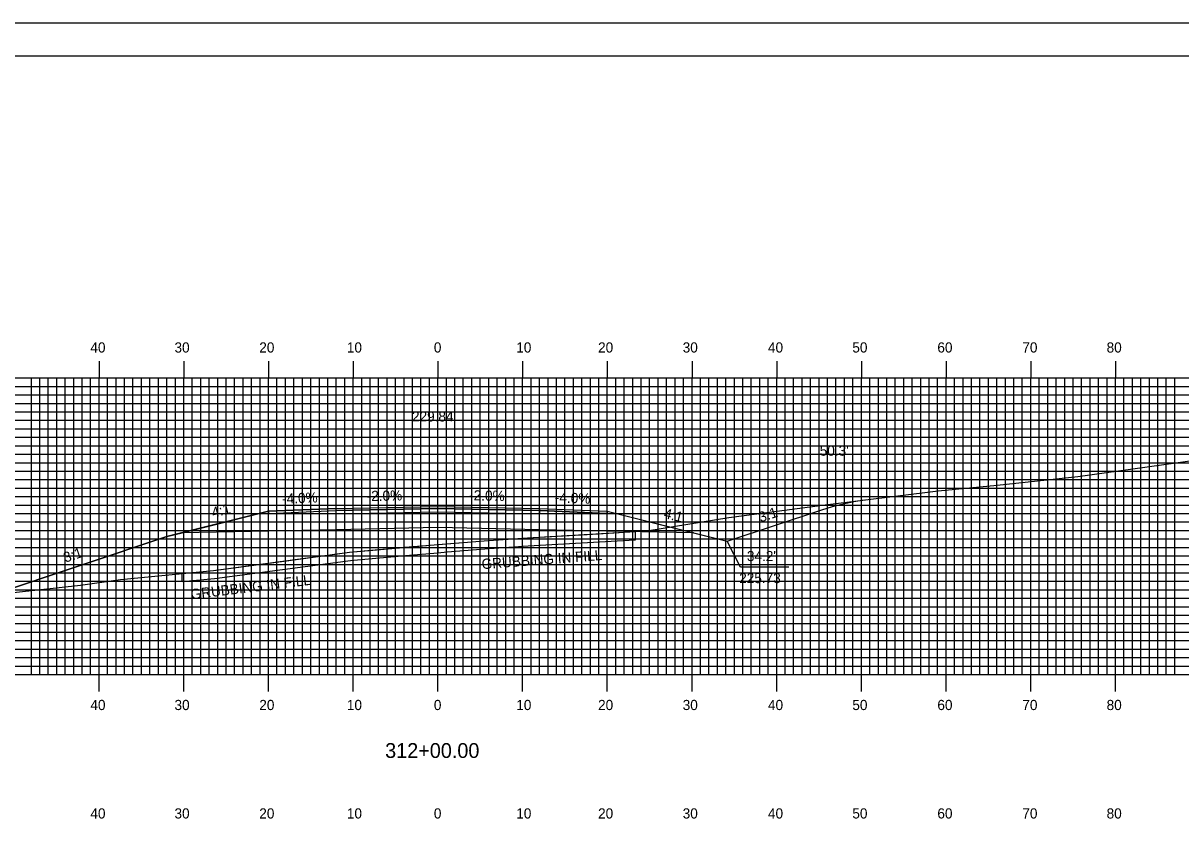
# Model space of a CAD drawing. Extents: x 1818457 to 1818800, y 442591 to 442811.
# Drawn here: x 1818573.7 to 1818710.4, y 442716.2 to 442810.5 of the extents above; entities that cross this region are included whole.
import ezdxf

# ---------------------------------------------------------------- set-up
doc = ezdxf.new("R2010")
doc.units = 0
for name, color, linetype in [('ANNOTATION', 7, 'Continuous'), ('BORDER', 7, 'Continuous'), ('D_Roadway_Centerline', 7, 'Continuous'), ('D_Roadway_Centerline_Text', 7, 'Continuous'), ('D_Roadway_Edge_Shoulder', 7, 'Continuous'), ('D_Roadway_Edge_TW', 7, 'Continuous'), ('D_Roadway_Pavement', 7, 'Continuous'), ('D_Roadway_SlopeLines', 7, 'Continuous'), ('D_Roadway_SubGrade', 7, 'Continuous'), ('D_Text_Standard', 7, 'Continuous'), ('GRUBBING IN FILL', 7, 'Continuous'), ('H_V ANNOTATION', 7, 'Continuous'), ('MAJOR', 7, 'Continuous'), ('MINOR', 7, 'Continuous'), ('PLOT BOUNDARY', 7, 'Continuous'), ('S_Roadway_Centerline', 7, 'Continuous')]:
    doc.layers.add(name, color=color, linetype=linetype)

msp = doc.modelspace()

# ---------------------------------------------------------------- linework, layer by layer
at = {"layer": 'ANNOTATION'}
msp.add_lwpolyline([(1818664.07, 442746.33), (1818658.38, 442746.33), (1818656.81, 442749.4)], dxfattribs=at)
at = {"layer": 'BORDER'}
msp.add_lwpolyline([(1818473.04, 442596.67), (1818793.04, 442596.67), (1818793.04, 442806.67), (1818473.04, 442806.67)], close=True, dxfattribs=at)
at = {"layer": 'D_Roadway_Centerline'}
msp.add_lwpolyline([(1818570, 442743.06), (1818590.64, 442749.94), (1818592.46, 442750.4), (1818602.64, 442752.94), (1818610.64, 442753.26), (1818622.64, 442753.5), (1818634.64, 442753.26), (1818642.64, 442752.94), (1818652.81, 442750.4), (1818656.81, 442749.4), (1818667.98, 442753.12), (1818669.23, 442753.51), (1818670.48, 442753.82), (1818671.73, 442754.08), (1818672.98, 442754.27)], dxfattribs=at)
at = {"layer": 'D_Roadway_Edge_Shoulder'}
for points in [[(1818610.64, 442753.26), (1818602.64, 442752.94), (1818602.64, 442752.69), (1818610.64, 442753.01)], [(1818634.64, 442753.26), (1818642.64, 442752.94), (1818642.64, 442752.69), (1818634.64, 442753.01)]]:
    msp.add_lwpolyline(points, close=True, dxfattribs=at)
at = {"layer": 'D_Roadway_Edge_TW'}
msp.add_lwpolyline([(1818610.64, 442753.01), (1818610.64, 442753.26), (1818622.64, 442753.5), (1818634.64, 442753.26), (1818634.64, 442753.01), (1818622.64, 442753.25)], close=True, dxfattribs=at)
at = {"layer": 'D_Roadway_Pavement'}
msp.add_lwpolyline([(1818610.64, 442752.59), (1818610.64, 442753.01), (1818622.64, 442753.25), (1818634.64, 442753.01), (1818634.64, 442752.59), (1818622.64, 442752.83)], close=True, dxfattribs=at)
at = {"layer": 'D_Roadway_SlopeLines'}
for points in [[(1818656.81, 442749.4), (1818667.98, 442753.12), (1818669.23, 442753.51), (1818670.48, 442753.82), (1818671.73, 442754.08), (1818672.98, 442754.27)], [(1818602.64, 442752.94), (1818590.64, 442749.94), (1818570, 442743.06)], [(1818642.64, 442752.94), (1818656.81, 442749.4)]]:
    msp.add_lwpolyline(points, dxfattribs=at)
at = {"layer": 'D_Roadway_SubGrade'}
msp.add_lwpolyline([(1818610.64, 442750.76), (1818592.46, 442750.4), (1818602.64, 442752.94), (1818602.64, 442752.69), (1818610.64, 442753.01), (1818622.64, 442753.25), (1818634.64, 442753.01), (1818642.64, 442752.69), (1818642.64, 442752.94), (1818652.81, 442750.4), (1818634.64, 442750.76), (1818622.64, 442751)], close=True, dxfattribs=at)
at = {"layer": 'GRUBBING IN FILL'}
for points in [[(1818645.92, 442750.54), (1818645.92, 442749.53), (1818639.6, 442749.18), (1818633.28, 442748.82), (1818628.71, 442748.49), (1818623.75, 442748.09), (1818622.64, 442748), (1818622.64, 442749), (1818628.62, 442749.49), (1818631.52, 442749.7), (1818633.22, 442749.81), (1818640.26, 442750.21)], [(1818645.92, 442750.54), (1818645.92, 442749.53), (1818639.6, 442749.18), (1818633.28, 442748.82), (1818628.71, 442748.49), (1818623.75, 442748.09), (1818622.64, 442748), (1818622.64, 442749), (1818628.62, 442749.49), (1818631.52, 442749.7), (1818633.22, 442749.81), (1818640.26, 442750.21)], [(1818592.46, 442745.59), (1818596.16, 442745.95), (1818604.18, 442747.02), (1818612.21, 442748.1), (1818615.88, 442748.43), (1818622.64, 442749), (1818622.64, 442748), (1818618.8, 442747.68), (1818613.14, 442747.18), (1818612.32, 442747.1), (1818604.3, 442746.03), (1818596.27, 442744.95), (1818592.46, 442744.59)], [(1818592.46, 442745.59), (1818596.16, 442745.95), (1818604.18, 442747.02), (1818612.21, 442748.1), (1818615.88, 442748.43), (1818622.64, 442749), (1818622.64, 442748), (1818618.8, 442747.68), (1818613.14, 442747.18), (1818612.32, 442747.1), (1818604.3, 442746.03), (1818596.27, 442744.95), (1818592.46, 442744.59)]]:
    msp.add_lwpolyline(points, close=True, dxfattribs=at)
at = {"layer": 'MAJOR'}
for p, q in [((1818582.64, 442770.67), (1818582.64, 442768.67)), ((1818592.64, 442770.67), (1818592.64, 442768.67)), ((1818602.64, 442770.67), (1818602.64, 442768.67)), ((1818612.64, 442770.67), (1818612.64, 442768.67)), ((1818622.64, 442770.67), (1818622.64, 442768.67)), ((1818632.64, 442770.67), (1818632.64, 442768.67)), ((1818642.64, 442770.67), (1818642.64, 442768.67)), ((1818652.64, 442770.67), (1818652.64, 442768.67)), ((1818662.64, 442770.67), (1818662.64, 442768.67)), ((1818672.64, 442770.67), (1818672.64, 442768.67)), ((1818682.64, 442770.67), (1818682.64, 442768.67)), ((1818692.64, 442770.67), (1818692.64, 442768.67)), ((1818702.64, 442770.67), (1818702.64, 442768.67)), ((1818482.64, 442768.67), (1818762.64, 442768.67)), ((1818482.64, 442768.67), (1818762.64, 442768.67)), ((1818582.64, 442733.67), (1818582.64, 442768.67)), ((1818592.64, 442733.67), (1818592.64, 442768.67)), ((1818602.64, 442733.67), (1818602.64, 442768.67)), ((1818612.64, 442733.67), (1818612.64, 442768.67)), ((1818622.64, 442733.67), (1818622.64, 442768.67)), ((1818632.64, 442733.67), (1818632.64, 442768.67)), ((1818642.64, 442733.67), (1818642.64, 442768.67)), ((1818652.64, 442733.67), (1818652.64, 442768.67)), ((1818662.64, 442733.67), (1818662.64, 442768.67)), ((1818672.64, 442733.67), (1818672.64, 442768.67)), ((1818682.64, 442733.67), (1818682.64, 442768.67)), ((1818692.64, 442733.67), (1818692.64, 442768.67)), ((1818702.64, 442733.67), (1818702.64, 442768.67)), ((1818482.64, 442763.67), (1818762.64, 442763.67)), ((1818482.64, 442758.67), (1818762.64, 442758.67)), ((1818482.64, 442753.67), (1818762.64, 442753.67)), ((1818482.64, 442748.67), (1818762.64, 442748.67)), ((1818482.64, 442743.67), (1818762.64, 442743.67)), ((1818482.64, 442738.67), (1818762.64, 442738.67)), ((1818482.64, 442733.67), (1818762.64, 442733.67)), ((1818482.64, 442733.67), (1818762.64, 442733.67)), ((1818582.64, 442731.66), (1818582.64, 442733.67)), ((1818592.64, 442731.66), (1818592.64, 442733.67)), ((1818602.64, 442731.66), (1818602.64, 442733.67)), ((1818612.64, 442731.66), (1818612.64, 442733.67)), ((1818622.64, 442731.66), (1818622.64, 442733.67)), ((1818632.64, 442731.66), (1818632.64, 442733.67)), ((1818642.64, 442731.66), (1818642.64, 442733.67)), ((1818652.64, 442731.66), (1818652.64, 442733.67)), ((1818662.64, 442731.66), (1818662.64, 442733.67)), ((1818672.64, 442731.66), (1818672.64, 442733.67)), ((1818682.64, 442731.66), (1818682.64, 442733.67)), ((1818692.64, 442731.66), (1818692.64, 442733.67)), ((1818702.64, 442731.66), (1818702.64, 442733.67))]:
    msp.add_line(p, q, dxfattribs=at)
at = {"layer": 'MINOR'}
for p, q in [((1818574.64, 442733.67), (1818574.64, 442768.67)), ((1818575.64, 442733.67), (1818575.64, 442768.67)), ((1818576.64, 442733.67), (1818576.64, 442768.67)), ((1818577.64, 442733.67), (1818577.64, 442768.67)), ((1818578.64, 442733.67), (1818578.64, 442768.67)), ((1818579.64, 442733.67), (1818579.64, 442768.67)), ((1818580.64, 442733.67), (1818580.64, 442768.67)), ((1818581.64, 442733.67), (1818581.64, 442768.67)), ((1818583.64, 442733.67), (1818583.64, 442768.67)), ((1818584.64, 442733.67), (1818584.64, 442768.67)), ((1818585.64, 442733.67), (1818585.64, 442768.67)), ((1818586.64, 442733.67), (1818586.64, 442768.67)), ((1818587.64, 442733.67), (1818587.64, 442768.67)), ((1818588.64, 442733.67), (1818588.64, 442768.67)), ((1818589.64, 442733.67), (1818589.64, 442768.67)), ((1818590.64, 442733.67), (1818590.64, 442768.67)), ((1818591.64, 442733.67), (1818591.64, 442768.67)), ((1818593.64, 442733.67), (1818593.64, 442768.67)), ((1818594.64, 442733.67), (1818594.64, 442768.67)), ((1818595.64, 442733.67), (1818595.64, 442768.67)), ((1818596.64, 442733.67), (1818596.64, 442768.67)), ((1818597.64, 442733.67), (1818597.64, 442768.67)), ((1818598.64, 442733.67), (1818598.64, 442768.67)), ((1818599.64, 442733.67), (1818599.64, 442768.67)), ((1818600.64, 442733.67), (1818600.64, 442768.67)), ((1818601.64, 442733.67), (1818601.64, 442768.67)), ((1818603.64, 442733.67), (1818603.64, 442768.67)), ((1818604.64, 442733.67), (1818604.64, 442768.67)), ((1818605.64, 442733.67), (1818605.64, 442768.67)), ((1818606.64, 442733.67), (1818606.64, 442768.67)), ((1818607.64, 442733.67), (1818607.64, 442768.67)), ((1818608.64, 442733.67), (1818608.64, 442768.67)), ((1818609.64, 442733.67), (1818609.64, 442768.67)), ((1818610.64, 442733.67), (1818610.64, 442768.67)), ((1818611.64, 442733.67), (1818611.64, 442768.67)), ((1818613.64, 442733.67), (1818613.64, 442768.67)), ((1818614.64, 442733.67), (1818614.64, 442768.67)), ((1818615.64, 442733.67), (1818615.64, 442768.67)), ((1818616.64, 442733.67), (1818616.64, 442768.67)), ((1818617.64, 442733.67), (1818617.64, 442768.67)), ((1818618.64, 442733.67), (1818618.64, 442768.67)), ((1818619.64, 442733.67), (1818619.64, 442768.67)), ((1818620.64, 442733.67), (1818620.64, 442768.67)), ((1818621.64, 442733.67), (1818621.64, 442768.67)), ((1818623.64, 442733.67), (1818623.64, 442768.67)), ((1818624.64, 442733.67), (1818624.64, 442768.67)), ((1818625.64, 442733.67), (1818625.64, 442768.67)), ((1818626.64, 442733.67), (1818626.64, 442768.67)), ((1818627.64, 442733.67), (1818627.64, 442768.67)), ((1818628.64, 442733.67), (1818628.64, 442768.67)), ((1818629.64, 442733.67), (1818629.64, 442768.67)), ((1818630.64, 442733.67), (1818630.64, 442768.67)), ((1818631.64, 442733.67), (1818631.64, 442768.67)), ((1818633.64, 442733.67), (1818633.64, 442768.67)), ((1818634.64, 442733.67), (1818634.64, 442768.67)), ((1818635.64, 442733.67), (1818635.64, 442768.67)), ((1818636.64, 442733.67), (1818636.64, 442768.67)), ((1818637.64, 442733.67), (1818637.64, 442768.67)), ((1818638.64, 442733.67), (1818638.64, 442768.67)), ((1818639.64, 442733.67), (1818639.64, 442768.67)), ((1818640.64, 442733.67), (1818640.64, 442768.67)), ((1818641.64, 442733.67), (1818641.64, 442768.67)), ((1818643.64, 442733.67), (1818643.64, 442768.67)), ((1818644.64, 442733.67), (1818644.64, 442768.67)), ((1818645.64, 442733.67), (1818645.64, 442768.67)), ((1818646.64, 442733.67), (1818646.64, 442768.67)), ((1818647.64, 442733.67), (1818647.64, 442768.67)), ((1818648.64, 442733.67), (1818648.64, 442768.67)), ((1818649.64, 442733.67), (1818649.64, 442768.67)), ((1818650.64, 442733.67), (1818650.64, 442768.67)), ((1818651.64, 442733.67), (1818651.64, 442768.67)), ((1818653.64, 442733.67), (1818653.64, 442768.67)), ((1818654.64, 442733.67), (1818654.64, 442768.67)), ((1818655.64, 442733.67), (1818655.64, 442768.67)), ((1818656.64, 442733.67), (1818656.64, 442768.67)), ((1818657.64, 442733.67), (1818657.64, 442768.67)), ((1818658.64, 442733.67), (1818658.64, 442768.67)), ((1818659.64, 442733.67), (1818659.64, 442768.67)), ((1818660.64, 442733.67), (1818660.64, 442768.67)), ((1818661.64, 442733.67), (1818661.64, 442768.67)), ((1818663.64, 442733.67), (1818663.64, 442768.67)), ((1818664.64, 442733.67), (1818664.64, 442768.67)), ((1818665.64, 442733.67), (1818665.64, 442768.67)), ((1818666.64, 442733.67), (1818666.64, 442768.67)), ((1818667.64, 442733.67), (1818667.64, 442768.67)), ((1818668.64, 442733.67), (1818668.64, 442768.67)), ((1818669.64, 442733.67), (1818669.64, 442768.67)), ((1818670.64, 442733.67), (1818670.64, 442768.67)), ((1818671.64, 442733.67), (1818671.64, 442768.67)), ((1818673.64, 442733.67), (1818673.64, 442768.67)), ((1818674.64, 442733.67), (1818674.64, 442768.67)), ((1818675.64, 442733.67), (1818675.64, 442768.67)), ((1818676.64, 442733.67), (1818676.64, 442768.67)), ((1818677.64, 442733.67), (1818677.64, 442768.67)), ((1818678.64, 442733.67), (1818678.64, 442768.67)), ((1818679.64, 442733.67), (1818679.64, 442768.67)), ((1818680.64, 442733.67), (1818680.64, 442768.67)), ((1818681.64, 442733.67), (1818681.64, 442768.67)), ((1818683.64, 442733.67), (1818683.64, 442768.67)), ((1818684.64, 442733.67), (1818684.64, 442768.67)), ((1818685.64, 442733.67), (1818685.64, 442768.67)), ((1818686.64, 442733.67), (1818686.64, 442768.67)), ((1818687.64, 442733.67), (1818687.64, 442768.67)), ((1818688.64, 442733.67), (1818688.64, 442768.67)), ((1818689.64, 442733.67), (1818689.64, 442768.67)), ((1818690.64, 442733.67), (1818690.64, 442768.67)), ((1818691.64, 442733.67), (1818691.64, 442768.67)), ((1818693.64, 442733.67), (1818693.64, 442768.67)), ((1818694.64, 442733.67), (1818694.64, 442768.67)), ((1818695.64, 442733.67), (1818695.64, 442768.67)), ((1818696.64, 442733.67), (1818696.64, 442768.67)), ((1818697.64, 442733.67), (1818697.64, 442768.67)), ((1818698.64, 442733.67), (1818698.64, 442768.67)), ((1818699.64, 442733.67), (1818699.64, 442768.67)), ((1818700.64, 442733.67), (1818700.64, 442768.67)), ((1818701.64, 442733.67), (1818701.64, 442768.67)), ((1818703.64, 442733.67), (1818703.64, 442768.67)), ((1818704.64, 442733.67), (1818704.64, 442768.67)), ((1818705.64, 442733.67), (1818705.64, 442768.67)), ((1818706.64, 442733.67), (1818706.64, 442768.67)), ((1818707.64, 442733.67), (1818707.64, 442768.67)), ((1818708.64, 442733.67), (1818708.64, 442768.67)), ((1818709.64, 442733.67), (1818709.64, 442768.67)), ((1818482.64, 442767.67), (1818762.64, 442767.67)), ((1818482.64, 442766.67), (1818762.64, 442766.67)), ((1818482.64, 442765.67), (1818762.64, 442765.67)), ((1818482.64, 442764.67), (1818762.64, 442764.67)), ((1818482.64, 442762.67), (1818762.64, 442762.67)), ((1818482.64, 442761.67), (1818762.64, 442761.67)), ((1818482.64, 442760.67), (1818762.64, 442760.67)), ((1818482.64, 442759.67), (1818762.64, 442759.67)), ((1818482.64, 442757.67), (1818762.64, 442757.67)), ((1818482.64, 442756.67), (1818762.64, 442756.67)), ((1818482.64, 442755.67), (1818762.64, 442755.67)), ((1818482.64, 442754.67), (1818762.64, 442754.67)), ((1818482.64, 442752.67), (1818762.64, 442752.67)), ((1818482.64, 442751.67), (1818762.64, 442751.67)), ((1818482.64, 442750.67), (1818762.64, 442750.67)), ((1818482.64, 442749.67), (1818762.64, 442749.67)), ((1818482.64, 442747.67), (1818762.64, 442747.67)), ((1818482.64, 442746.67), (1818762.64, 442746.67)), ((1818482.64, 442745.67), (1818762.64, 442745.67)), ((1818482.64, 442744.67), (1818762.64, 442744.67)), ((1818482.64, 442742.67), (1818762.64, 442742.67)), ((1818482.64, 442741.67), (1818762.64, 442741.67)), ((1818482.64, 442740.67), (1818762.64, 442740.67)), ((1818482.64, 442739.67), (1818762.64, 442739.67)), ((1818482.64, 442737.67), (1818762.64, 442737.67)), ((1818482.64, 442736.67), (1818762.64, 442736.67)), ((1818482.64, 442735.67), (1818762.64, 442735.67)), ((1818482.64, 442734.67), (1818762.64, 442734.67))]:
    msp.add_line(p, q, dxfattribs=at)
at = {"layer": 'PLOT BOUNDARY'}
msp.add_lwpolyline([(1818456.85, 442590.55), (1818796.85, 442590.55), (1818796.85, 442810.55), (1818456.85, 442810.55)], close=True, dxfattribs=at)
at = {"layer": 'S_Roadway_Centerline'}
msp.add_lwpolyline([(1818565.65, 442742.58), (1818580.46, 442744.22), (1818585.17, 442744.89), (1818596.16, 442745.95), (1818612.21, 442748.1), (1818613.05, 442748.17), (1818618.72, 442748.68), (1818628.62, 442749.49), (1818629.81, 442749.58), (1818633.22, 442749.81), (1818647.29, 442750.61), (1818656.97, 442752.19), (1818668.04, 442753.65), (1818681.71, 442755.35), (1818688.66, 442756.02), (1818698.19, 442757.04), (1818709.76, 442758.67), (1818715.73, 442759.51), (1818722.62, 442760.52), (1818747.81, 442762.07), (1818749, 442762.13), (1818762.64, 442763.07)], dxfattribs=at)

# ---------------------------------------------------------------- texts
at = {"layer": 'ANNOTATION'}
for s, rotation, p in [('-4.0%', 2.2906, (1818604.27, 442753.81)), ('-2.0%', 1.1458, (1818614.24, 442754.13)), ('-2.0%', 358.8542, (1818626.32, 442754.23)), ('-4.0%', 357.7094, (1818636.43, 442753.99)), ('4:1', 14.0362, (1818596.09, 442752.17)), ('4:1', 345.9638, (1818649.23, 442752.16)), ('3:1', 18.4348, (1818660.74, 442751.61)), ('3:1', 18.4348, (1818578.66, 442746.86))]:
    msp.add_text(s, height=1.2, rotation=rotation, dxfattribs=at).set_placement(p)
for s, p in [("34.2'", (1818659.12, 442747.05)), ('225.73', (1818658.21, 442744.45))]:
    msp.add_text(s, height=1.2, dxfattribs=at).set_placement(p)
at = {"layer": 'D_Roadway_Centerline'}
for s, p in [('C', (1818622.63, 442753.5)), ('L', (1818622.64, 442753.49))]:
    msp.add_text(s, height=0.0146, dxfattribs=at).set_placement(p)
at = {"layer": 'D_Roadway_Centerline_Text'}
msp.add_text('229.84', height=1.2, dxfattribs=at).set_placement((1818619.58, 442763.53))
at = {"layer": 'D_Text_Standard'}
msp.add_text("50.3'", height=1.2, dxfattribs=at).set_placement((1818667.72, 442759.49))
at = {"layer": 'GRUBBING IN FILL'}
for rotation, p in [(4.3574, (1818627.85, 442746.1)), (6.9672, (1818593.53, 442742.53))]:
    msp.add_text('GRUBBING IN FILL', height=1.2, rotation=rotation, dxfattribs=at).set_placement(p)
at = {"layer": 'H_V ANNOTATION'}
for s, height, p in [('40', 1.2, (1818581.61, 442771.67)), ('30', 1.2, (1818591.54, 442771.67)), ('20', 1.2, (1818601.55, 442771.67)), ('10', 1.2, (1818611.89, 442771.67)), ('0', 1.2, (1818622.16, 442771.67)), ('10', 1.2, (1818631.89, 442771.67)), ('20', 1.2, (1818641.55, 442771.67)), ('30', 1.2, (1818651.54, 442771.67)), ('40', 1.2, (1818661.61, 442771.67)), ('50', 1.2, (1818671.57, 442771.67)), ('60', 1.2, (1818681.61, 442771.67)), ('70', 1.2, (1818691.64, 442771.67)), ('80', 1.2, (1818701.59, 442771.67)), ('40', 1.2, (1818581.61, 442729.47)), ('30', 1.2, (1818591.54, 442729.47)), ('20', 1.2, (1818601.55, 442729.47)), ('10', 1.2, (1818611.89, 442729.47)), ('0', 1.2, (1818622.16, 442729.47)), ('10', 1.2, (1818631.89, 442729.47)), ('20', 1.2, (1818641.55, 442729.47)), ('30', 1.2, (1818651.54, 442729.47)), ('40', 1.2, (1818661.61, 442729.47)), ('50', 1.2, (1818671.57, 442729.47)), ('60', 1.2, (1818681.61, 442729.47)), ('70', 1.2, (1818691.64, 442729.47)), ('80', 1.2, (1818701.59, 442729.47)), ('312+00.00', 1.75, (1818616.41, 442723.82)), ('40', 1.2, (1818581.61, 442716.67)), ('30', 1.2, (1818591.54, 442716.67)), ('20', 1.2, (1818601.55, 442716.67)), ('10', 1.2, (1818611.89, 442716.67)), ('0', 1.2, (1818622.16, 442716.67)), ('10', 1.2, (1818631.89, 442716.67)), ('20', 1.2, (1818641.55, 442716.67)), ('30', 1.2, (1818651.54, 442716.67)), ('40', 1.2, (1818661.61, 442716.67)), ('50', 1.2, (1818671.57, 442716.67)), ('60', 1.2, (1818681.61, 442716.67)), ('70', 1.2, (1818691.64, 442716.67)), ('80', 1.2, (1818701.59, 442716.67))]:
    msp.add_text(s, height=height, dxfattribs=at).set_placement(p)

doc.saveas('drawing.dxf')
